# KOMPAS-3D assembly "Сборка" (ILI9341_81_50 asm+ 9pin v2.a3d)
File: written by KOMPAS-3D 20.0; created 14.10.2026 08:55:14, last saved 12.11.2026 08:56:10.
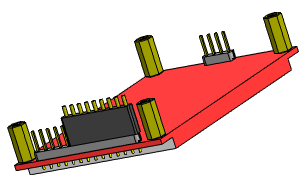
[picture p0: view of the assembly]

Document properties: Полное имя файла: D:\myProjects\Progect_esp32\box_compas\монитор\ILI9341_81_50 asm+ 9pin v2.a3d

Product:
- Part/product: Сборка
    Масса: 0.133106
  - Component [detail]: Деталь  | Масса: 0.00276261; source file: ..\разъемы\pbs_9.m3d
  - Component [detail]: Деталь  | Масса: 0.123412; source file: ILI9341_81х50.m3d
  - Component [detail]: Деталь  | Масса: 0.00180884; source file: ..\разъемы\pls_14.m3d
  - Component [detail]: Деталь  | Масса: 0.000505328; source file: ..\разъемы\pls_4.m3d
  - Component [detail]: Деталь  | qty 4  | Масса: 0.00115433; source file: ..\прочее\PCHSS-11.m3d

Referenced files in D:\myProjects\Progect_esp32\box_compas\монитор\: ILI9341_81х50.m3d
Referenced files in D:\myProjects\Progect_esp32\box_compas\разъемы\: pls_14.m3d, pls_4.m3d, pbs_9.m3d
Referenced files in D:\myProjects\Progect_esp32\box_compas\прочее\: PCHSS-11.m3d
Referenced files in D:\RicWork\Project-EPS32\box_compas\прочее\: PCHSS-11.m3d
